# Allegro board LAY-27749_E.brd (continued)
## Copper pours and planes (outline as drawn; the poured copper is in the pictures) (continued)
USB_OVDD on BOTTOM: 82.11,150.56 82.74,150.56 82.99,150.81 82.99,151.38 83.19,151.57 85.66,151.57 86.61,152.53 88.77,152.53 89.41,153.16 89.66,153.16 90.11,153.61 90.49,153.61 90.68,153.42 90.93,153.42 91.57,154.05 91.57,154.31 91.44,154.43 91.19,154.43 91,154.24 90.61,154.24 90.42,154.43 90.17,154.43 89.53,153.8 89.15,153.8 88.52,153.16 85.98,153.16 85.66,152.84 81.32,152.84 80.39,151.92 78.28,151.92 76.99,150.62 71.55,150.62 71.37,150.44 71.37,148.84 71.5,148.72 73.28,148.72 73.66,149.1 76.2,149.1 76.45,149.35 77.52,149.35 78,148.87 80.42,148.87 81.15,149.61 81.66,149.61 81.92,149.86 81.92,150.37
USB_SVDD on TOP: 102.11,127.64 102.36,127.38 102.36,126.75 102.74,126.36 102.74,124.71 102.36,124.33 98.68,124.33 98.55,124.46 98.55,126.62 99.57,127.64
USB_SVDD on L10_INT_4: 93.98,154.1 93.98,139.57 95.12,138.43 95.12,133.35 98.93,129.54 100.84,129.54 101.85,128.52 101.85,126.62 101.47,126.24 96.14,126.24 89.79,132.59 89.79,140.34 89.66,140.46 89.66,154.13 89.99,154.46 93.62,154.46
X1_GND on TOP (solid shape): 116.19,85.97 116.75,85.97 117.07,85.65 117.9,85.65 117.98,85.57 117.98,85.39 117.91,85.32 115.36,85.32 115.1,85.58 113.15,85.58 112.98,85.75 112.98,87.15 112.85,87.27 111.33,87.27 111.07,87.02 111.07,84.99 111.2,84.86 112.6,84.86 112.73,84.73 112.73,83.34 112.85,83.21 114.63,83.21 115.57,84.15 117.88,84.15 118.01,84.02 118.01,83.92 117.91,83.82 117.12,83.82 116.89,83.59 115.65,83.59 114.76,82.7 113.49,82.7 113.23,82.45 110.38,82.45 109.65,83.17 109.65,87 110.9,88.24 113.92,88.24
X1_GND on L2_GND_1: 110.9,88.24 113.92,88.24 116.2,85.95 116.76,85.95 117.07,85.65 117.91,85.65 118.01,85.55 118.01,83.92 117.91,83.82 117.09,83.82 116.87,83.59 115.65,83.59 114.76,82.7 113.49,82.7 113.23,82.45 110.36,82.45 109.65,83.16 109.65,87
XVDD on TOP (solid shape): 36.17,153.67 36.17,148.26 37.09,147.35 39.78,147.35 40.21,146.91 40.21,143.66 39.9,143.36 35.41,143.36 35.13,143.64 35.13,144.22 34.82,144.53 31.93,144.53 31.7,144.75 31.7,151.23 31.07,151.87 31.07,153.59 31.4,153.92 35.92,153.92
XVDD on TOP: 95.96,190.98 95.76,191.19 95.76,191.9 95.63,192.02 94.36,192.02 93.98,191.64 93.6,191.64 93.34,191.9 92.71,191.9 92.58,191.77 92.58,191.26 92.2,190.88 90.93,190.88 90.55,191.26 90.55,191.77 91.57,192.79 97.28,192.79 97.41,192.66 97.41,192.28 97.28,192.15 96.9,192.15 96.52,191.77 96.52,191.21 96.29,190.98
XVDD on TOP: 96.52,132.33 99.57,132.33 99.82,132.59 99.82,133.6 100.08,133.86 101.35,133.86 101.6,133.6 101.6,132.72 101.98,132.33 107.31,132.33 107.7,132.72 107.7,133.73 107.82,133.86 108.33,133.86 108.46,133.73 108.46,132.59 108.79,132.26 111.61,132.26 111.76,132.11 111.76,130.18 111.12,129.54 100.71,129.54 95.89,124.71 95.89,121.41 95.86,121.39 95.86,120.45 93.85,118.44 86.44,118.44 85.88,119 85.88,121.92 86.28,122.33 90.25,122.33 91.24,123.32 91.24,128.7 91.57,129.03 94.49,129.03 95,129.54 95,131.57 95.25,131.83 96.01,131.83
XVDD on BOTTOM: 96.39,192.02 94.61,192.02 93.85,192.79 93.47,192.79 93.34,192.66 93.34,192.41 92.96,192.02 85.19,192.02 84.51,191.34 84.51,187.86 85.36,187.01 89.34,187.01 91.31,188.98 94.74,188.98 96.65,190.88 96.65,191.77
XVDD on BOTTOM: 42.37,153.92 43.43,152.86 43.43,114 44.68,112.75 53.49,112.75 62.69,121.95 89.23,121.95 90.09,121.08 90.09,107.11 88.93,105.94 80.16,105.94 76,101.78 67.79,101.78 59.16,93.14 27.58,93.14 23.77,96.95 23.77,116.51 24.87,117.6 24.87,123.04 23.77,124.13 23.77,152.91 24.79,153.92
XVDD on L12_INT_5: 87.4,189.15 88.62,190.37 88.62,198.32 86.84,200.1 68.83,200.1 42.24,173.51 42.24,164.41 38.01,160.19 33.29,160.19 31.32,158.22 31.32,150.44 33.38,148.39 45.85,148.39 54.15,156.69 54.15,165 78.31,189.15
Z5402 on TOP: 240.11,236.85 240.36,237.11 240.36,238.33 240,238.68 238.58,238.68 238.2,238.3 238.2,237.16 238.51,236.85
Z5402 on L12_INT_5: 238.61,241.35 255.32,241.35 255.78,240.89 255.78,238.25 254.76,237.24 238.3,237.24 237.64,237.9 237.64,240.39
N16616368 on TOP (solid shape): 43.43,215.01 43.43,206.5 40.74,203.81 37.62,203.81 34.04,200.23 34.04,197.97 33.78,197.71 33.78,197.61 33.77,197.6 33.72,197.5 33.71,197.38 33.73,197.26 33.78,197.15 33.78,196.08 33.66,195.96 33.15,195.96 32.9,196.21 32.9,196.21 32.64,196.47 32.64,201.93 36.55,205.84 39.88,205.84 41.53,207.49 41.53,213.23 40.89,213.87 40.89,215.26 41.02,215.39 43.05,215.39
N30741197 on BOTTOM: 52.53,73.38 54.13,73.38 54.51,73 54.51,71.68 54.31,71.48 52.2,71.48 52.04,71.63 52.04,72.9
N30741197 on L10_INT_4: 59.31,74.09 59.51,73.89 59.51,72.69 58.37,71.55 53.75,71.55 53.37,71.93 53.37,73.76 53.7,74.09
N31714350 on TOP: 31.57,101.8 32.56,101.8 33.12,101.24 33.12,100.33 33,100.2 32.64,100.2 32.46,100.38 32.46,101.02 32.11,101.37 31.55,101.37 31.52,101.4 31.52,101.75
N31714354 on TOP: 33.58,101.68 34.11,101.68 34.22,101.57 34.22,100.33 34.11,100.23 33.63,100.23 33.5,100.36 33.5,101.6
N31714416 on TOP: 30.81,102.31 32.16,102.31 34.24,104.39 39.7,104.39 40.03,104.06 40.03,101.75 39.68,101.4 34.9,101.4 34.29,102.01 30.81,102.01 30.79,102.03 30.79,102.29
N31714501 on TOP (solid shape): 30.05,105.11 30.05,104.65 30.46,104.24 30.46,103.23 30.43,103.2 30.13,103.2 30.08,103.25 30.08,103.73 29.52,104.29 28.7,104.29 28.45,104.55 28.45,105.16 28.6,105.31 29.85,105.31
N31717308 on TOP (solid shape): 177.55,193.93 177.55,192.15 177.42,192.02 176.53,192.02 175.39,193.17 172.47,193.17 172.34,193.29 172.34,194.94 172.59,195.2 176.28,195.2
N31718323 on TOP (solid shape): 33.79,192.27 33.79,191.99 33.78,191.93 33.77,191.88 33.77,191.37 32.64,190.24 32.64,187.32 32.52,187.19 30.87,187.19 30.61,187.45 30.61,191.13 31.88,192.4 33.66,192.4
N31789783 on TOP: 30.18,162.89 31.11,162.89 31.7,162.31 31.7,161.39 31.57,161.26 31.22,161.26 31.04,161.44 31.04,162.08 30.68,162.43 30.12,162.43 30.1,162.46 30.1,162.81
N31789787 on TOP: 32.16,162.74 32.69,162.74 32.79,162.64 32.79,161.39 32.69,161.29 32.21,161.29 32.08,161.42 32.08,162.66
N31789873 on TOP (solid shape): 38.28,165.46 38.61,165.13 38.61,162.81 38.25,162.46 33.48,162.46 32.87,163.07 29.39,163.07 29.36,163.09 29.36,163.35 29.39,163.37 30.73,163.37 32.82,165.46 33.07,165.46
N31789971 on TOP (solid shape): 28.63,166.17 28.63,165.71 29.03,165.3 29.03,164.29 29.01,164.26 28.7,164.26 28.65,164.31 28.65,164.8 28.09,165.35 27.28,165.35 27.03,165.61 27.03,166.22 27.18,166.37 28.42,166.37
N31884800 on TOP: 31.75,138.25 32.74,138.25 33.3,137.69 33.3,136.78 33.17,136.65 32.82,136.65 32.64,136.83 32.64,137.46 32.28,137.82 31.73,137.82 31.7,137.85 31.7,138.2
N31884804 on TOP: 33.76,138.13 34.29,138.13 34.39,138.02 34.39,136.78 34.29,136.68 33.81,136.68 33.68,136.8 33.68,138.05
N31884868 on TOP: 30.99,138.76 32.34,138.76 34.42,140.84 39.88,140.84 40.21,140.51 40.21,138.2 39.85,137.85 35.08,137.85 34.47,138.46 30.99,138.46 30.96,138.48 30.96,138.73
N31884952 on TOP: 30.61,139.65 30.3,139.65 30.25,139.7 30.25,140.18 29.69,140.74 28.88,140.74 28.63,141 28.63,141.6 28.78,141.76 30.02,141.76 30.23,141.55 30.23,141.1 30.63,140.69 30.63,139.67
N31888261 on TOP: 249.25,88.52 249.25,89.46 249.83,90.04 250.75,90.04 250.88,89.92 250.88,89.56 250.7,89.38 250.06,89.38 249.71,89.03 249.71,88.47 249.68,88.44 249.33,88.44
N31888263 on TOP: 249.4,90.5 249.4,91.04 249.5,91.14 250.75,91.14 250.85,91.04 250.85,90.55 250.72,90.43 249.48,90.43
N31888274 on TOP: 248.77,87.73 248.77,89.08 246.68,91.16 246.68,96.62 247.01,96.95 249.33,96.95 249.68,96.6 249.68,91.82 249.07,91.21 249.07,87.73 249.05,87.71 248.79,87.71
N31888295 on TOP: 247.88,87.35 247.88,87.05 247.83,87 247.35,87 246.79,86.44 246.79,85.62 246.53,85.37 245.92,85.37 245.77,85.52 245.77,86.77 245.97,86.97 246.43,86.97 246.84,87.38 247.85,87.38
N32105138 on TOP (solid shape): 113.79,57.73 113.79,55.83 113.41,55.45 111.12,55.45 110.74,55.83 110.74,57.73 110.87,57.86 113.67,57.86
N32105138 on L10_INT_4: 110.31,58.27 117.07,58.27 120.5,54.84 124.31,54.84 126.14,56.67 129.13,56.67 130.38,55.42 137.06,55.42 137.46,55.02 137.46,50.16 137.01,49.71 116.1,49.71 113.03,52.78 110.19,52.78 109.75,53.21 109.75,57.71
N32112200 on TOP: 140.94,45.52 142.67,45.52 142.88,45.31 142.88,44.27 142.65,44.04 140.69,44.04 140.49,44.25 140.49,45.06
N32112200 on L12_INT_5: 136.6,48.29 138.02,48.29 139.83,46.48 141.43,46.48 141.99,45.92 141.99,44.5 141.6,44.12 137.08,44.12 136.25,44.96 136.25,47.93
N32114233 on TOP (solid shape): 155.96,57.73 155.96,55.83 155.57,55.45 153.29,55.45 152.91,55.83 152.91,57.73 153.03,57.86 155.83,57.86
N32114233 on L10_INT_4: 152.48,58.27 159.23,58.27 162.66,54.84 166.47,54.84 168.3,56.67 171.3,56.67 172.54,55.42 179.22,55.42 179.63,55.02 179.63,50.16 179.17,49.71 158.27,49.71 155.47,52.5 153.42,52.5 151.92,54 151.92,57.71
N32114439 on TOP: 182.83,45.36 184.78,45.36 185.04,45.11 185.04,44.27 184.81,44.04 182.85,44.04 182.65,44.25 182.65,45.19
N32114439 on L12_INT_5: 178.64,48.41 181.31,48.41 184.05,45.67 184.05,44.32 183.87,44.15 179.3,44.15 178.38,45.06 178.38,48.16
N32123083 on TOP: 204.85,63.76 204.85,64.7 205.44,65.28 206.35,65.28 206.48,65.15 206.48,64.8 206.3,64.62 205.66,64.62 205.31,64.26 205.31,63.7 205.28,63.68 204.93,63.68
N32123087 on TOP: 205,65.74 205,66.27 205.1,66.37 206.35,66.37 206.45,66.27 206.45,65.79 206.32,65.66 205.08,65.66
N32123169 on TOP: 204.37,62.97 204.37,64.31 202.29,66.4 202.29,71.86 202.62,72.19 204.93,72.19 205.28,71.83 205.28,67.06 204.67,66.45 204.67,62.97 204.65,62.94 204.39,62.94
N32123255 on TOP: 203.48,62.59 203.48,62.28 203.43,62.23 202.95,62.23 202.39,61.67 202.39,60.86 202.13,60.61 201.52,60.61 201.37,60.76 201.37,62 201.57,62.21 202.03,62.21 202.44,62.61 203.45,62.61

Small or netless copper shapes (teardrops, artwork), in the pictures only: 4034 on TOP, 778 on BOTTOM, 92 on L3_INT_1, 84 on L5_INT_2, 23 on L7_INT_3, 135 on L12_INT_5, 77 on L14_INT_6

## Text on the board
BOTTOM: 170-27749 REV E | 19 | L16_SS
Ref Des/Silkscreen Bottom: 21 | SECONDARY SILKSCREEN
User.Comments: 1 | 8 | B2 | B4 | B1 | B3 | A1 | A3 | A2 | A4 | 4 | 03 | 20 | PRIMARY SOLDERMASK | SECONDARY SOLDERMASK | 16 LAYER | TOP | IN1 | IN2 | GND1 | GND2 | GND3 | IN3 | GND5 | GND6 | VCC | IN4 | GND4 | IN6 | BOTTOM | VCC1 | IN5 | NCDRILL | PASTEMASK_TOP | PASTEMASK_BOTTOM | 1/1 | 3
TOP: 04 | L1_PS
Ref Des/Silkscreen Top: A | T4240RDB-PB REV E | 02 | PRIMARY SILKSCREEN
L2_GND_1: 05 | L2_GND_1
L3_INT_1: 06 | L3_INT_1
L4_GND_2: 07 | L4_GND_2
L5_INT_2: 08 | L5_INT_2
L6_GND_3: 09 | L6_GND_3
L7_INT_3: 10 | L7_INT_3
L8_PWR_1: 11 | L8_PWR_1
L9_PWR_2: 12 | L9_PWR_2
L10_INT_4: 13 | L10_INT_4
L11_GND_4: 14 | L11_GND_4
L12_INT_5: 15 | L12_INT_5
L13_GND_5: 16 | L13_GND_5
L14_INT_6: 17 | L14_INT_6
L15_GND_6: 18 | L15_GND_6
NCROUTE_PATH: V-CUT | 253.00 | 5.00 | 2.50 | CUTOUT | 250.50 | 70.31 | 86.5 | 7.5 | 5
XSECTION_CHART: LAYERS | L1_PS | L3_INT_1 | L5_INT_2 | L7_INT_3 | L10_INT_4 | L12_INT_5 | L14_INT_6 | L16_SS | TRACE WIDTH | 4.64 | 3.43 | --- | SE | IMPEDANCE | 50 | 3.6 | 3.92 | TRACE SPACING | 4.4 | 6.08 | 90 | 3.37 | DIFF | 10.13 | 7.4 | 100 | REFERENCE LAYER | 11,13 | 13,15 | 15,17 | 2,4 | 4,6 | 6,8 | 17 | 2 | L13 L13_GND_5 PLANE - 1OZ_COPPER 1.2 MIL | L2 L2_GND_1 PLANE - 1OZ_COPPER 1.2 MIL | L12 L12_INT_5 CONDUCTOR - 1/2OZ_COPPER 0.6 MIL | L15 L15_GND_6 PLANE - 1OZ_COPPER 1.2 MIL | L16 BOTTOM CONDUCTOR - COPPER 2.1 MIL | *  DIELECTRIC - EM-827B 4.29 MIL | *  SURFACE - AIR 0 MIL | L1 TOP CONDUCTOR - COPPER 2.1 MIL | *  DIELECTRIC - EM-827B 3.06 MIL | *  DIELECTRIC - EM-827 3.5 MIL | L3 L3_INT_1 CONDUCTOR - 1/2OZ_COPPER 0.6 MIL | *  DIELECTRIC - EM-827B 3.5 MIL | *  DIELECTRIC - EM-827 4.29 MIL | *  DIELECTRIC - EM-827 2.99 MIL | L11 L11_GND_4 PLANE - 1OZ_COPPER 1.2 MIL | L14 L14_INT_6 CONDUCTOR - 1/2OZ_COPPER 0.6 MIL | L7 L7_INT_3 CONDUCTOR - 1/2OZ_COPPER 0.6 MIL | L8 L8_PWR_1 PLANE - 1OZ_COPPER 1.2 MIL | L4 L4_GND_2 PLANE - 1OZ_COPPER 1.2 MIL | L5 L5_INT_2 CONDUCTOR - 1/2OZ_COPPER 0.6 MIL | L9 L9_PWR_2 PLANE - 1OZ_COPPER 1.2 MIL | L10 L10_INT_4 CONDUCTOR - 1/2OZ_COPPER 0.6 MIL | L6 L6_GND_3 PLANE - 1OZ_COPPER 1.2 MIL | DESIGN CROSS SECTION CHART | ___________________________ | TOTAL THICKNESS 73.25 MIL | SCALE : NONE | TOLERANCE +/-10% | 1-16 | 16. | DETAIL | IMPEDANCE REQUIREMENTS | IMPEDANCE TOLERANCE IS 10% | LAYER STACKUP | B | A
DISPLAY_TOP: A | RST Button | F | PWR Button | E | NOR FLASH | NAND FLASH | D | G | PWR I2C | CPU FAN | J | H | 10G PHY JTAG | (DEFAULT) | JP2 | 1-2 | 2-3 | AT24C02C | ADDRESS | 0X50 | 0X51 | JP4 | BOOT DEVICE SEL | JTAG MODE CHOOSE | NORMAL MODE | JTAG MODE | JP1 | NOR | CS0 | CS1 | NAND | CPLD JTAG | I2C2 | JTAG | DIMM3 | DIMM1 | DIMM2 | 22 | SECONDARY PASTEMASK
DISPLAY_BOTTOM: A | B | 1 | 2 | 01 | PRIMARY PASTEMASK
BODY_CENTER: 23. | 22.
User.8: OF22
User.10: 22. THIS FAB3_VIAFILL.ART SHOWS LOCATIONS OF VIA-IN-PAD TO BE FILLED. | 1/1 | 3
User.11: 1/1 | 2 | 3
User.13: FIGURE | FINISHED_SIZE | 10.0 | 10.1 | 12.0 | 12.1 | 20.0 | 26.0 | 28.0 | 32.0 | 35.0 | 36.0 | 37.0 | 39.0 | 40.0 | 41.0 | 43.0 | 44.0 | 47.0 | 51.0 | 56.0 | 57.0 | 63.0 | 64.0 | 91.0 | 135.0 | 158.0 | 50.0 | 59.0 | 61.0 | 93.0 | 96.0 | 118.0 | 120.0 | 128.0 | 96.0x71.0 | DRILL CHART: TOP to BOTTOM | ALL UNITS ARE IN MILS | TOLERANCE_DRILL | +0.0/-10.0 | +0.0/-10.1 | +0.0/-12.0 | +0.0/-12.1 | +0.0/-20.0 | +2.0/-2.0 | +3.0/-3.0 | PLATED | NON-PLATED | QTY | 4303 | 270 | 14 | 184 | 676 | 96 | 12 | 818 | 120 | 24 | 20 | 2 | 61 | 8 | 4 | 32 | 6 | 16 | 10 | 3 | 6785 | TOTAL HOLES:
